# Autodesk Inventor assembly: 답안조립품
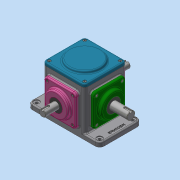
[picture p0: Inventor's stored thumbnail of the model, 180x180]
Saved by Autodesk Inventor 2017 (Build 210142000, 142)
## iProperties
Part Number: 답안조립품
Material: 일반
Document SubType Name: Assembly
Designer: MRC
Mass: 3235.88 g
Surface Area: 2651.66 cm^2
Volume: 866.536 cm^3
Density: 3.73427 g/cm^3
Author: MRC
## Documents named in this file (16)
- C:\Users\MRC\Desktop\620307V1003\답안조립품.iam
- C:\Users\MRC\Desktop\620307V1003\본체.ipt
- C:\Users\MRC\Desktop\620307V1003\개스킷.ipt
- C:\Users\MRC\Desktop\620307V1003\메인베벨기어.ipt
- C:\Users\MRC\Desktop\620307V1003\메인축.ipt
- C:\Users\MRC\Desktop\620307V1003\메인커버.ipt
- C:\Users\MRC\Desktop\620307V1003\베어링 6203.ipt
- C:\Users\MRC\Desktop\620307V1003\베어링 6204.ipt
- C:\Users\MRC\Desktop\620307V1003\볼트 M4.ipt
- C:\Users\MRC\Desktop\620307V1003\상부커버.ipt
- C:\Users\MRC\Desktop\620307V1003\서브베벨기어.ipt
- C:\Users\MRC\Desktop\620307V1003\서브축.ipt
- C:\Users\MRC\Desktop\620307V1003\서브커버.ipt
- C:\Users\MRC\Desktop\620307V1003\오일 실 17 32 8.ipt
- C:\Users\MRC\Desktop\620307V1003\오일 실 20 35 8.ipt
- C:\Users\MRC\Desktop\620307V1003\키 4x4.ipt
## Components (1 placed, 1 different names)
1. 개스킷:1
